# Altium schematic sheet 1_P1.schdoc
size 307 x 218 mm; Symbol: Drawing-Symbol_A4; Device: Drawing-Symbol_A4; @Project Name: Pomodorino Timer; @Page Count: 1; @Update Date: 2025-01-27; @Create Date: 2025-01-25; @Schematic Name: Schematic1; @Page No: 1; @Page Name: P1; Company: EasyEDA.com; Version: V1.0; Page Size: A4; @Create Time: 11:26:55; @Update Time: 20:56:58; Width: 1170; Height: 825; Region Start: 1; X Region Count: 6; Y Region Count: 4; Blade Width: 10; Title Block Position: 3; @Board Name: Board1
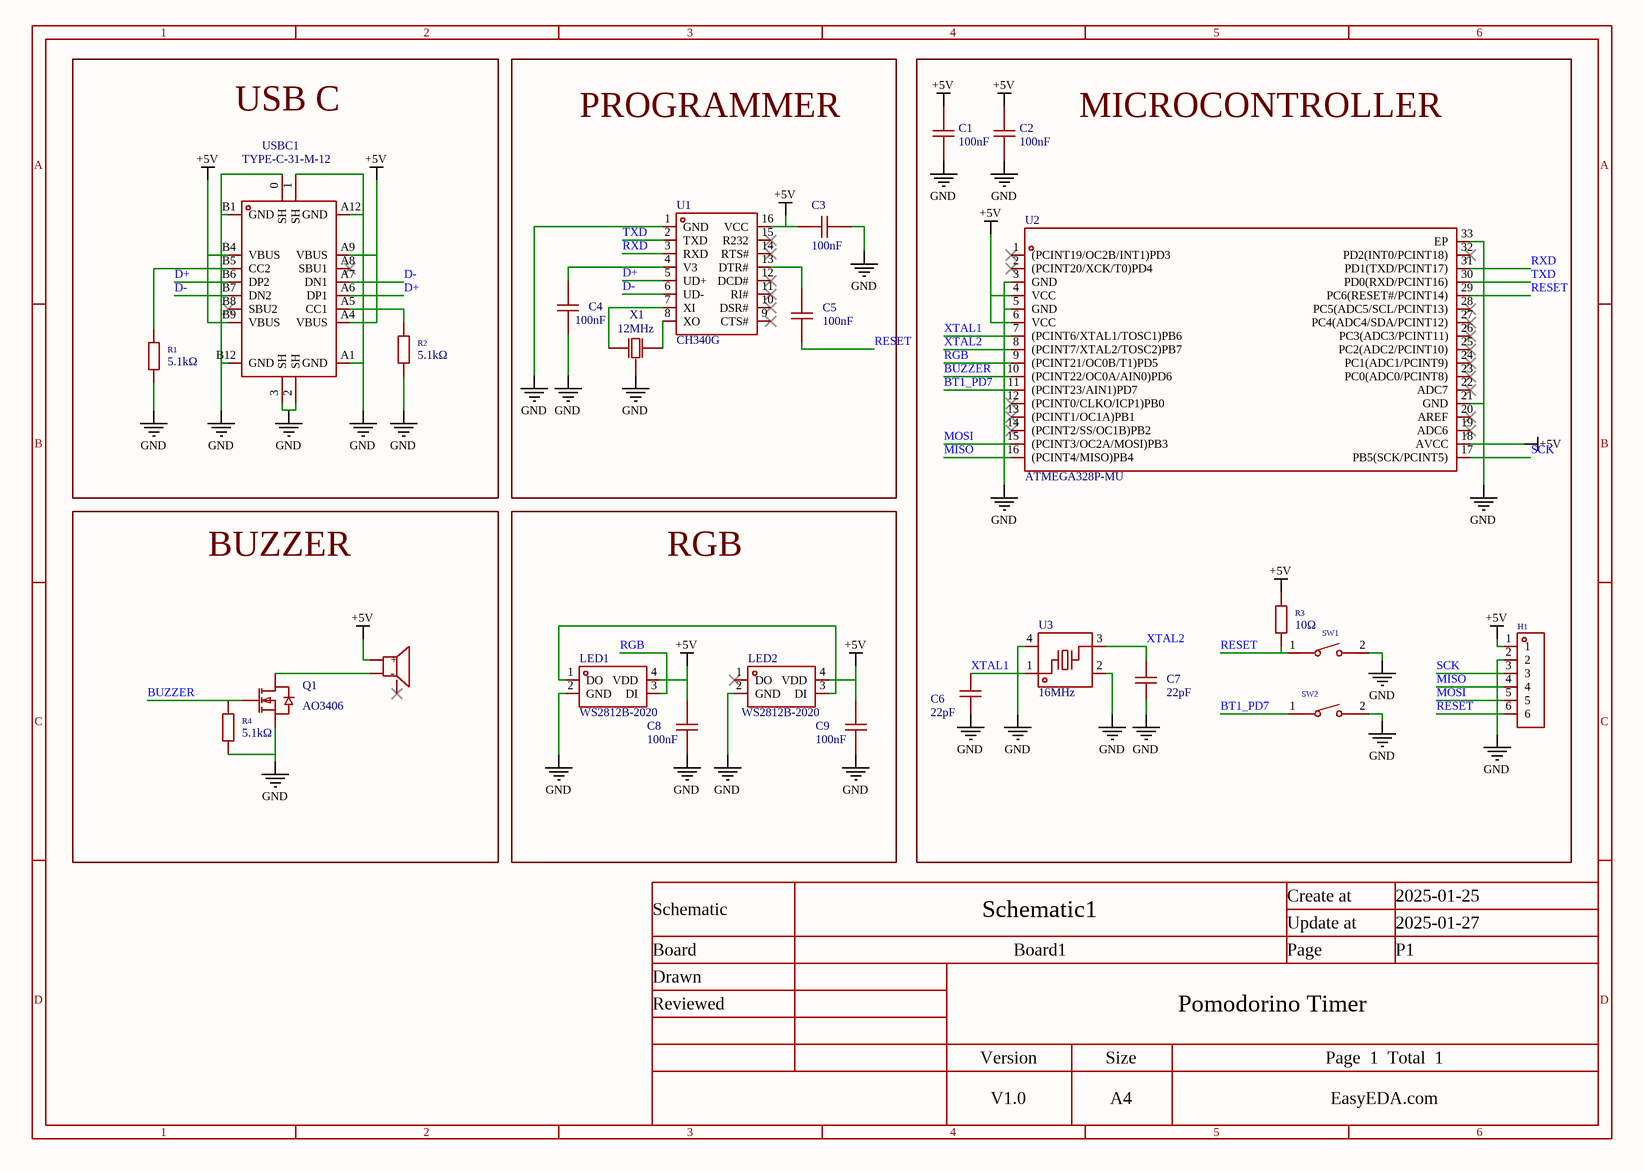
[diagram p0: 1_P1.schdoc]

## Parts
BUZZER1  4kHz  [BUZ-SMD_L5.0-W5.5-P4.60]  (value not drawn)
C1  100nF  [C0402]
C2  100nF  [C0402]
C3  100nF  [C0402]
C4  100nF  [C0402]
C5  100nF  [C0402]
C6  22pF  [C0402]
C7  22pF  [C0402]
C8  100nF  [C0402]
C9  100nF  [C0402]
H1  (no value)  [HDR-TH_6P-P2.54-V-F]
LED1  WS2812B-2020  [LED-SMD_4P-L2.0-W2.0-TL_WS2812B-2020]
LED2  WS2812B-2020  [LED-SMD_4P-L2.0-W2.0-TL_WS2812B-2020]
Q1  AO3406  [SOT-23-3_L2.9-W1.6-P1.90-LS2.8-BR]
R1  5.1kΩ  [R0402]
R2  5.1kΩ  [R0402]
R3  10Ω  [R0402]
R4  5.1kΩ  [R0402]
SW1  TS-1088-AR02016  [SW-SMD_L3.9-W3.0-P4.45]  (value not drawn)
SW2  TS-1088-AR02016  [SW-SMD_L3.9-W3.0-P4.45]  (value not drawn)
U1  CH340G  [SOIC-16_L9.9-W3.9-P1.27-LS6.0-BL]
U2  ATMEGA328P-MU  [HVQFN-32_L5.0-W5.0-P0.50-TL-EP3.1]
U3  16MHz  [CRYSTAL-SMD_4P-L3.2-W2.5-BL_SIT8008BI]
USBC1  TYPE-C-31-M-12  [USB-C_SMD-TYPE-C-31-M-12]
X1  12MHz  [CRYSTAL-SMD_3P-L3.2-W1.3-P1.20-L-1]

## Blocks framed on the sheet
USB C: R1 R2 USBC1
PROGRAMMER: C3-C5 U1 X1
MICROCONTROLLER: C1 C2 C6 C7 H1 R3 SW1 SW2 U2 U3
BUZZER: BUZZER1 Q1 R4
RGB: C8 C9 LED1 LED2

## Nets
+5V: BUZZER1.1(+) C1.1 C2.1 C3.2 C8.1 C9.1 H1.1 LED1.4(VDD) LED2.4(VDD) R2.2 R3.2 U1.16(VCC) U2.4(VCC) U2.6(VCC) U2.18(AVCC) USBC1.A4(VBUS) USBC1.A5(CC1) USBC1.A9(VBUS) USBC1.B4(VBUS) USBC1.B9(VBUS)
GND: C1.2 C2.2 C3.1 C4.2 C6.1 C7.1 C8.2 C9.2 H1.2 LED1.2(GND) LED2.2(GND) Q1.2(S) R1.1 R2.1 R4.1 SW1.2 SW2.2 U1.1(GND) U2.3(GND) U2.5(GND) U2.21(GND) U2.33(EP) U3.2(GND) U3.4(GND) USBC1.0(SH) USBC1.1(SH) USBC1.2(SH) USBC1.3(SH) USBC1.A1(GND) USBC1.A12(GND) USBC1.B1(GND) USBC1.B12(GND) X1.2(GND)
BT1_PD7: SW2.1 U2.11((PCINT23/AIN1)PD7)
BUZZER: Q1.1(G) R4.2 U2.10((PCINT22/OC0A/AIN0)PD6)
D+: U1.5(UD+) USBC1.A6(DP1) USBC1.B6(DP2)
D-: U1.6(UD-) USBC1.A7(DN1) USBC1.B7(DN2)
MISO: H1.4 U2.16((PCINT4/MISO)PB4)
MOSI: H1.5 U2.15((PCINT3/OC2A/MOSI)PB3)
RESET: C5.1 H1.6 R3.1 SW1.1 U2.29(PC6(RESET#/PCINT14))
RGB: LED1.3(DI) U2.9((PCINT21/OC0B/T1)PD5)
RXD: U1.3(RXD) U2.31(PD1(TXD/PCINT17))
SCK: H1.3 U2.17(PB5(SCK/PCINT5))
TXD: U1.2(TXD) U2.30(PD0(RXD/PCINT16))
XTAL1: C6.2 U2.7((PCINT6/XTAL1/TOSC1)PB6) U3.1
XTAL2: C7.2 U2.8((PCINT7/XTAL2/TOSC2)PB7) U3.3
NetBUZZER1_2: BUZZER1.2(-) Q1.3(D)
NetC4_1: C4.1 U1.4(V3)
NetC5_2: C5.2 U1.13(DTR#)
NetLED1_1: LED1.1(DO) LED2.3(DI)
NetR1_2: R1.2 USBC1.B5(CC2)
NetU1_7: U1.7(XI) X1.3(OUTPUT)
NetU1_8: U1.8(XO) X1.1(INPUT)

Not connected (* = marked no-connect by the designer): BUZZER1 3(NC)*; LED2 1(DO)*; U1 9(CTS#)* 10(DSR#)* 11(RI#)* 12(DCD#)* 14(RTS#)* 15(R232)*; U2 1((PCINT19/OC2B/INT1)PD3)* 2((PCINT20/XCK/T0)PD4)* 12((PCINT0/CLKO/ICP1)PB0)* 13((PCINT1/OC1A)PB1)* 14((PCINT2/SS/OC1B)PB2)* 19(ADC6)* 20(AREF)* 22(ADC7)* 23(PC0(ADC0/PCINT8))* 24(PC1(ADC1/PCINT9))* 25(PC2(ADC2/PCINT10))* 26(PC3(ADC3/PCINT11))* 27(PC4(ADC4/SDA/PCINT12))* 28(PC5(ADC5/SCL/PCINT13))* 32(PD2(INT0/PCINT18))*; USBC1 A8(SBU1)* B8(SBU2)*

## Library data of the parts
BUZZER1 = MLT-5020: Manufacturer: 华能; Add into BOM: yes; Driver Circuitry: Passive (external drive)
C1-C3 C5 C8 C9 = CL05B104KB54PNC: Manufacturer: SAMSUNG(三星); Add into BOM: yes; Tolerance: ±10%
C4 = CT41G-0402-2X1-16V-0.1μF-K(N): Manufacturer: TORCH(火炬); Add into BOM: yes; Tolerance: ±10%
C6 C7 = 0402CG220J500NT: Manufacturer: FH(风华); Add into BOM: yes; Tolerance: ±5%
H1 = HDR-F_2.54_1x6P: Manufacturer: BOOMELE(博穆精密); Manufacturer Part: 2.54-1*6P母; Symbol: Header-Female-2.54_1x6; Convert to PCB: yes
LED1 LED2 = WS2812B-2020: Manufacturer: worldsemi; Add into BOM: yes; Wavelength: 515.6nm；622.5nm；470.4nm
Q1 = AO3406_C5379102: Manufacturer: MSKSEMI(美森科); Add into BOM: yes; Type: 1 N-channel; Drain Source On Resistance (RDS(on)@Vgs,Id): 35mΩ@10V,3.5A; Power Dissipation (Pd): 278mW; Gate Threshold Voltage (Vgs(th)@Id): 1.5V@250uA; Total Gate Charge (Qg@Vgs): 3.1nC@10V; Input Capacitance (Ciss@Vds): 245pF@25V; Reverse Transfer Capacitance (Crss@Vds): 78pF@25V
R1 R2 R4 = 0402WGF5101TCE: Manufacturer: UNI-ROYAL(厚声); Add into BOM: yes; Tolerance: ±1%; Temperature Coefficient: ±100ppm/℃
R3 = 0402WGF100JTCE: Manufacturer: UNI-ROYAL(厚声); Add into BOM: yes; Tolerance: ±1%; Temperature Coefficient: ±200ppm/℃
SW1 SW2 = TS-1088-AR02016: Manufacturer: XUNPU(讯普); Add into BOM: yes; Circuit: SPST; Actuator Style: Round Button; Operating Force: 160gf; Switch Length: 4mm; Switch Width: 3mm; Switch Height: 2mm; Strike Gundam: 不带; Contact Current: 50mA; Voltage Rating (DC): 12V; Insulation Resistance: 100MΩ; Actuator/Cap Color: Black; Pin Style: SMDSplicing; Mechanical Life: 10万次
U1 = CH340G: Manufacturer: WCH(南京沁恒); Add into BOM: yes; Applications Function: USB to UART; Supply Voltage: 5V；3.3V; Data Rate: 2Mbps
U2 = ATMEGA328P-MU_C7499261: Manufacturer: MICROCHIP(美国微芯); Add into BOM: yes; CPU Core: AVR; CPU Maximum Speed: 20MHz; Number of I/O: 23; ADC (Bit): 10bit; Voltage - Supply: 1.8V~5.5V
U3 = S3216000222080C3: Manufacturer: JGHC(晶光华); Add into BOM: yes; Crystal Type: Surface Mount Crystal; Normal temperature Frequency Tolerance: ±30ppm; Frequency Stability(Full temperature range): ±20ppm; Equivalent Series Resistance (ESR): 80Ω
USBC1 = TYPE-C-31-M-12: Manufacturer: 韩国韩荣; Add into BOM: yes; Connector Type: Type-C; Gender: Female; Number of Contacts: 16P; Number of Ports: 1; Current Rating - Power (Max): 5A
X1 = CSTNE12M0G550000R0: Manufacturer: muRata(村田); Add into BOM: yes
